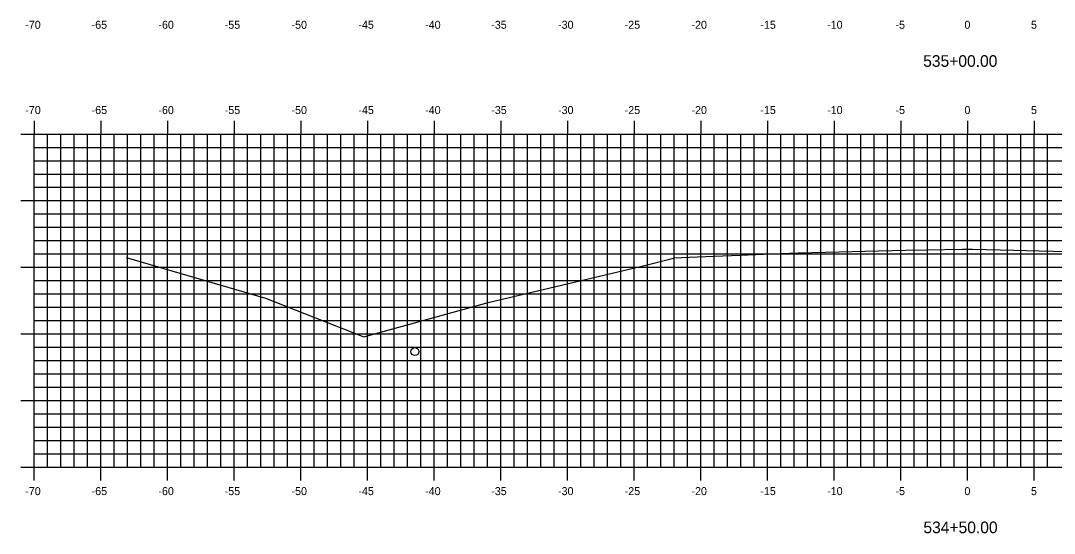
# Model space of a CAD drawing. Extents: x 1170543 to 1177585, y 609599 to 610623.
# Drawn here: x 1177208.2 to 1177285.7, y 610272.8 to 610311.3 of the extents above; entities that cross this region are included whole.
import ezdxf

# ---------------------------------------------------------------- set-up
doc = ezdxf.new("R2010")
doc.units = 0
for name, color, linetype in [('H_V ANNOTATION', 7, 'Continuous'), ('MAJOR', 7, 'Continuous'), ('MINOR', 7, 'Continuous'), ('S_Drainage_Invert', 7, 'Continuous'), ('S_Roadway_Centerline', 7, 'Continuous')]:
    doc.layers.add(name, color=color, linetype=linetype)

msp = doc.modelspace()

# ---------------------------------------------------------------- linework, layer by layer
at = {"layer": 'MAJOR'}
for p, q in [((1177209.168, 610303.803), (1177209.168, 610302.801)), ((1177214.168, 610303.803), (1177214.168, 610302.801)), ((1177219.168, 610303.803), (1177219.168, 610302.801)), ((1177224.168, 610303.803), (1177224.168, 610302.801)), ((1177229.168, 610303.803), (1177229.168, 610302.801)), ((1177234.168, 610303.803), (1177234.168, 610302.801)), ((1177239.168, 610303.803), (1177239.168, 610302.801)), ((1177244.168, 610303.803), (1177244.168, 610302.801)), ((1177249.168, 610303.803), (1177249.168, 610302.801)), ((1177254.168, 610303.803), (1177254.168, 610302.801)), ((1177259.168, 610303.803), (1177259.168, 610302.801)), ((1177264.168, 610303.803), (1177264.168, 610302.801)), ((1177269.168, 610303.803), (1177269.168, 610302.801)), ((1177274.168, 610303.803), (1177274.168, 610302.801)), ((1177279.168, 610303.803), (1177279.168, 610302.801)), ((1177284.168, 610303.803), (1177284.168, 610302.801)), ((1177208.166, 610302.801), (1177209.168, 610302.801)), ((1177209.168, 610302.801), (1177349.168, 610302.801)), ((1177209.168, 610277.801), (1177209.168, 610302.801)), ((1177209.168, 610277.801), (1177209.168, 610302.801)), ((1177209.168, 610302.801), (1177349.168, 610302.801)), ((1177214.168, 610277.801), (1177214.168, 610302.801)), ((1177219.168, 610277.801), (1177219.168, 610302.801)), ((1177224.168, 610277.801), (1177224.168, 610302.801)), ((1177229.168, 610277.801), (1177229.168, 610302.801)), ((1177234.168, 610277.801), (1177234.168, 610302.801)), ((1177239.168, 610277.801), (1177239.168, 610302.801)), ((1177244.168, 610277.801), (1177244.168, 610302.801)), ((1177249.168, 610277.801), (1177249.168, 610302.801)), ((1177254.168, 610277.801), (1177254.168, 610302.801)), ((1177259.168, 610277.801), (1177259.168, 610302.801)), ((1177264.168, 610277.801), (1177264.168, 610302.801)), ((1177269.168, 610277.801), (1177269.168, 610302.801)), ((1177274.168, 610277.801), (1177274.168, 610302.801)), ((1177279.168, 610277.801), (1177279.168, 610302.801)), ((1177284.168, 610277.801), (1177284.168, 610302.801)), ((1177208.166, 610297.801), (1177209.168, 610297.801)), ((1177209.168, 610297.801), (1177349.168, 610297.801)), ((1177208.166, 610292.801), (1177209.168, 610292.801)), ((1177209.168, 610292.801), (1177349.168, 610292.801)), ((1177208.166, 610287.801), (1177209.168, 610287.801)), ((1177209.168, 610287.801), (1177349.168, 610287.801)), ((1177208.166, 610282.801), (1177209.168, 610282.801)), ((1177209.168, 610282.801), (1177349.168, 610282.801)), ((1177208.166, 610277.801), (1177209.168, 610277.801)), ((1177209.168, 610277.801), (1177349.168, 610277.801)), ((1177209.168, 610277.801), (1177349.168, 610277.801)), ((1177209.168, 610276.799), (1177209.168, 610277.801)), ((1177214.168, 610276.799), (1177214.168, 610277.801)), ((1177219.168, 610276.799), (1177219.168, 610277.801)), ((1177224.168, 610276.799), (1177224.168, 610277.801)), ((1177229.168, 610276.799), (1177229.168, 610277.801)), ((1177234.168, 610276.799), (1177234.168, 610277.801)), ((1177239.168, 610276.799), (1177239.168, 610277.801)), ((1177244.168, 610276.799), (1177244.168, 610277.801)), ((1177249.168, 610276.799), (1177249.168, 610277.801)), ((1177254.168, 610276.799), (1177254.168, 610277.801)), ((1177259.168, 610276.799), (1177259.168, 610277.801)), ((1177264.168, 610276.799), (1177264.168, 610277.801)), ((1177269.168, 610276.799), (1177269.168, 610277.801)), ((1177274.168, 610276.799), (1177274.168, 610277.801)), ((1177279.168, 610276.799), (1177279.168, 610277.801)), ((1177284.168, 610276.799), (1177284.168, 610277.801))]:
    msp.add_line(p, q, dxfattribs=at)
at = {"layer": 'MINOR'}
for p, q in [((1177210.168, 610277.801), (1177210.168, 610302.801)), ((1177211.168, 610277.801), (1177211.168, 610302.801)), ((1177212.168, 610277.801), (1177212.168, 610302.801)), ((1177213.168, 610277.801), (1177213.168, 610302.801)), ((1177215.168, 610277.801), (1177215.168, 610302.801)), ((1177216.168, 610277.801), (1177216.168, 610302.801)), ((1177217.168, 610277.801), (1177217.168, 610302.801)), ((1177218.168, 610277.801), (1177218.168, 610302.801)), ((1177220.168, 610277.801), (1177220.168, 610302.801)), ((1177221.168, 610277.801), (1177221.168, 610302.801)), ((1177222.168, 610277.801), (1177222.168, 610302.801)), ((1177223.168, 610277.801), (1177223.168, 610302.801)), ((1177225.168, 610277.801), (1177225.168, 610302.801)), ((1177226.168, 610277.801), (1177226.168, 610302.801)), ((1177227.168, 610277.801), (1177227.168, 610302.801)), ((1177228.168, 610277.801), (1177228.168, 610302.801)), ((1177230.168, 610277.801), (1177230.168, 610302.801)), ((1177231.168, 610277.801), (1177231.168, 610302.801)), ((1177232.168, 610277.801), (1177232.168, 610302.801)), ((1177233.168, 610277.801), (1177233.168, 610302.801)), ((1177235.168, 610277.801), (1177235.168, 610302.801)), ((1177236.168, 610277.801), (1177236.168, 610302.801)), ((1177237.168, 610277.801), (1177237.168, 610302.801)), ((1177238.168, 610277.801), (1177238.168, 610302.801)), ((1177240.168, 610277.801), (1177240.168, 610302.801)), ((1177241.168, 610277.801), (1177241.168, 610302.801)), ((1177242.168, 610277.801), (1177242.168, 610302.801)), ((1177243.168, 610277.801), (1177243.168, 610302.801)), ((1177245.168, 610277.801), (1177245.168, 610302.801)), ((1177246.168, 610277.801), (1177246.168, 610302.801)), ((1177247.168, 610277.801), (1177247.168, 610302.801)), ((1177248.168, 610277.801), (1177248.168, 610302.801)), ((1177250.168, 610277.801), (1177250.168, 610302.801)), ((1177251.168, 610277.801), (1177251.168, 610302.801)), ((1177252.168, 610277.801), (1177252.168, 610302.801)), ((1177253.168, 610277.801), (1177253.168, 610302.801)), ((1177255.168, 610277.801), (1177255.168, 610302.801)), ((1177256.168, 610277.801), (1177256.168, 610302.801)), ((1177257.168, 610277.801), (1177257.168, 610302.801)), ((1177258.168, 610277.801), (1177258.168, 610302.801)), ((1177260.168, 610277.801), (1177260.168, 610302.801)), ((1177261.168, 610277.801), (1177261.168, 610302.801)), ((1177262.168, 610277.801), (1177262.168, 610302.801)), ((1177263.168, 610277.801), (1177263.168, 610302.801)), ((1177265.168, 610277.801), (1177265.168, 610302.801)), ((1177266.168, 610277.801), (1177266.168, 610302.801)), ((1177267.168, 610277.801), (1177267.168, 610302.801)), ((1177268.168, 610277.801), (1177268.168, 610302.801)), ((1177270.168, 610277.801), (1177270.168, 610302.801)), ((1177271.168, 610277.801), (1177271.168, 610302.801)), ((1177272.168, 610277.801), (1177272.168, 610302.801)), ((1177273.168, 610277.801), (1177273.168, 610302.801)), ((1177275.168, 610277.801), (1177275.168, 610302.801)), ((1177276.168, 610277.801), (1177276.168, 610302.801)), ((1177277.168, 610277.801), (1177277.168, 610302.801)), ((1177278.168, 610277.801), (1177278.168, 610302.801)), ((1177280.168, 610277.801), (1177280.168, 610302.801)), ((1177281.168, 610277.801), (1177281.168, 610302.801)), ((1177282.168, 610277.801), (1177282.168, 610302.801)), ((1177283.168, 610277.801), (1177283.168, 610302.801)), ((1177285.168, 610277.801), (1177285.168, 610302.801)), ((1177209.168, 610301.801), (1177349.168, 610301.801)), ((1177209.168, 610301.801), (1177210.17, 610301.801)), ((1177209.168, 610300.801), (1177349.168, 610300.801)), ((1177209.168, 610300.801), (1177210.17, 610300.801)), ((1177209.168, 610299.801), (1177349.168, 610299.801)), ((1177209.168, 610299.801), (1177210.17, 610299.801)), ((1177209.168, 610298.801), (1177349.168, 610298.801)), ((1177209.168, 610298.801), (1177210.17, 610298.801)), ((1177209.168, 610296.801), (1177349.168, 610296.801)), ((1177209.168, 610296.801), (1177210.17, 610296.801)), ((1177209.168, 610295.801), (1177349.168, 610295.801)), ((1177209.168, 610295.801), (1177210.17, 610295.801)), ((1177209.168, 610294.801), (1177349.168, 610294.801)), ((1177209.168, 610294.801), (1177210.17, 610294.801)), ((1177209.168, 610293.801), (1177349.168, 610293.801)), ((1177209.168, 610293.801), (1177210.17, 610293.801)), ((1177209.168, 610291.801), (1177349.168, 610291.801)), ((1177209.168, 610291.801), (1177210.17, 610291.801)), ((1177209.168, 610290.801), (1177349.168, 610290.801)), ((1177209.168, 610290.801), (1177210.17, 610290.801)), ((1177209.168, 610289.801), (1177349.168, 610289.801)), ((1177209.168, 610289.801), (1177210.17, 610289.801)), ((1177209.168, 610288.801), (1177349.168, 610288.801)), ((1177209.168, 610288.801), (1177210.17, 610288.801)), ((1177209.168, 610286.801), (1177349.168, 610286.801)), ((1177209.168, 610286.801), (1177210.17, 610286.801)), ((1177209.168, 610285.801), (1177349.168, 610285.801)), ((1177209.168, 610285.801), (1177210.17, 610285.801)), ((1177209.168, 610284.801), (1177349.168, 610284.801)), ((1177209.168, 610284.801), (1177210.17, 610284.801)), ((1177209.168, 610283.801), (1177349.168, 610283.801)), ((1177209.168, 610283.801), (1177210.17, 610283.801)), ((1177209.168, 610281.801), (1177349.168, 610281.801)), ((1177209.168, 610281.801), (1177210.17, 610281.801)), ((1177209.168, 610280.801), (1177349.168, 610280.801)), ((1177209.168, 610280.801), (1177210.17, 610280.801)), ((1177209.168, 610279.801), (1177349.168, 610279.801)), ((1177209.168, 610279.801), (1177210.17, 610279.801)), ((1177209.168, 610278.801), (1177349.168, 610278.801)), ((1177209.168, 610278.801), (1177210.17, 610278.801))]:
    msp.add_line(p, q, dxfattribs=at)
at = {"layer": 'S_Drainage_Invert'}
msp.add_circle((1177237.726, 610286.469), 0.3, dxfattribs=at)
at = {"layer": 'S_Roadway_Centerline'}
msp.add_lwpolyline([(1177216.081, 610293.544), (1177226.513, 610290.47), (1177233.891, 610287.58), (1177243.206, 610290.147), (1177254.73, 610292.885), (1177257.002, 610293.452), (1177257.177, 610293.499), (1177258.288, 610293.547), (1177259.542, 610293.598), (1177261.465, 610293.684), (1177264.542, 610293.818), (1177266.465, 610293.876), (1177269.542, 610293.967), (1177271.463, 610294.012), (1177274.542, 610294.081), (1177276.102, 610294.111), (1177278.774, 610294.163), (1177279.133, 610294.161), (1177279.542, 610294.159), (1177282.628, 610294.083), (1177284.542, 610294.037), (1177287.634, 610293.948)], dxfattribs=at)

# ---------------------------------------------------------------- texts
at = {"layer": 'H_V ANNOTATION'}
for s, height, p in [('-70', 0.6, (1177208.509, 610310.701)), ('-65', 0.6, (1177213.485, 610310.701)), ('-60', 0.6, (1177218.493, 610310.701)), ('-55', 0.6, (1177223.464, 610310.701)), ('-50', 0.6, (1177228.472, 610310.701)), ('-45', 0.6, (1177233.485, 610310.701)), ('-40', 0.6, (1177238.493, 610310.701)), ('-35', 0.6, (1177243.448, 610310.701)), ('-30', 0.6, (1177248.456, 610310.701)), ('-25', 0.6, (1177253.453, 610310.701)), ('-20', 0.6, (1177258.461, 610310.701)), ('-15', 0.6, (1177263.624, 610310.701)), ('-10', 0.6, (1177268.632, 610310.701)), ('-5', 0.6, (1177273.758, 610310.701)), ('0', 0.6, (1177278.927, 610310.701)), ('5', 0.6, (1177283.919, 610310.701)), ('535+00.00', 0.875, (1177275.835, 610307.844)), ('-70', 0.6, (1177208.509, 610304.301)), ('-65', 0.6, (1177213.485, 610304.301)), ('-60', 0.6, (1177218.493, 610304.301)), ('-55', 0.6, (1177223.464, 610304.301)), ('-50', 0.6, (1177228.472, 610304.301)), ('-45', 0.6, (1177233.485, 610304.301)), ('-40', 0.6, (1177238.493, 610304.301)), ('-35', 0.6, (1177243.448, 610304.301)), ('-30', 0.6, (1177248.456, 610304.301)), ('-25', 0.6, (1177253.453, 610304.301)), ('-20', 0.6, (1177258.461, 610304.301)), ('-15', 0.6, (1177263.624, 610304.301)), ('-10', 0.6, (1177268.632, 610304.301)), ('-5', 0.6, (1177273.758, 610304.301)), ('0', 0.6, (1177278.927, 610304.301)), ('5', 0.6, (1177283.919, 610304.301)), ('-70', 0.6, (1177208.509, 610275.701)), ('-65', 0.6, (1177213.485, 610275.701)), ('-60', 0.6, (1177218.493, 610275.701)), ('-55', 0.6, (1177223.464, 610275.701)), ('-50', 0.6, (1177228.472, 610275.701)), ('-45', 0.6, (1177233.485, 610275.701)), ('-40', 0.6, (1177238.493, 610275.701)), ('-35', 0.6, (1177243.448, 610275.701)), ('-30', 0.6, (1177248.456, 610275.701)), ('-25', 0.6, (1177253.453, 610275.701)), ('-20', 0.6, (1177258.461, 610275.701)), ('-15', 0.6, (1177263.624, 610275.701)), ('-10', 0.6, (1177268.632, 610275.701)), ('-5', 0.6, (1177273.758, 610275.701)), ('0', 0.6, (1177278.927, 610275.701)), ('5', 0.6, (1177283.919, 610275.701)), ('534+50.00', 0.875, (1177275.851, 610272.844))]:
    msp.add_text(s, height=height, dxfattribs=at).set_placement(p)

doc.saveas('drawing.dxf')
